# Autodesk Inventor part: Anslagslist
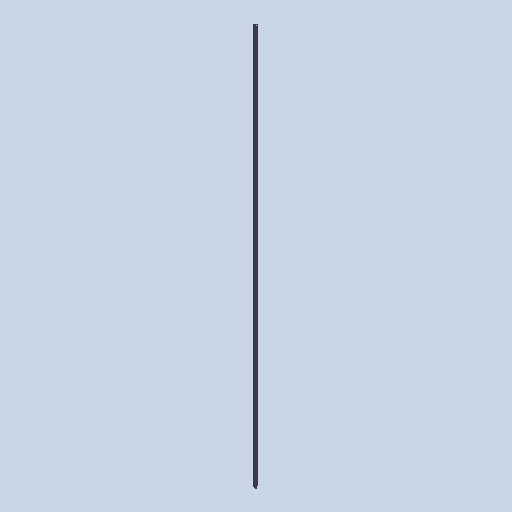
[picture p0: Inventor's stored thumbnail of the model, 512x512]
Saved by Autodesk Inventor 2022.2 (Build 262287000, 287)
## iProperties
Created: 2019-06
Part Number: Anslagslist
Material: Aluminum 6061, Welded
Document SubType Name: Modeling
Designer: cl
Density: 2.7 g/cm^3
Appearance: Weld - Aluminum
Author: cl
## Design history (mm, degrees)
sketch "Sketch1"
  geometry: L1 (0, 0)-(-19, 6.245); L2 (-19, 6.245)-(-29, 6.245); L3 (0, -3.158)-(-10, 0.129); L4 (0, 0)-(0, -3.158); L5 (-10, 0.129)-(-10, -14.871); L6 (-10, -14.871)-(-13, -14.871); L7 (-13, -14.871)-(-13, 1.115); L8 (-13, 1.115)-(-19.48, 3.245); L9 (-19.48, 3.245)-(-29, 3.245); L10 (-29, 3.245)-(-29, 6.245)
  constraints: 20 end point, 3 perpendicular, 2 horizontal, 2 parallel, 2 vertical, 1 collinear
  dimensions: "d0" = 3 distance between parallel lines of L3 L1; "d1" = 15 distance of L3.end L5.end; "d2" = 3 distance of L5.end L6.end; "d3" = 10 horizontal distance of L3.end L3.start; "d4" = 10 distance of L1.end L2.end; "d5" = 3 distance between parallel lines of L9 L2; "d6" = 20 distance of L1.start L1.end; "d8" = 29 distance between parallel lines of L10 L4
extrude "Extrusion1" new body sketch "Sketch1" distance "d11" = 2991 (computed from Daghöjd); taper "d12" = 0 deg
body "Solid1"
other parameters: "BladBredd" = 1338.66667, "Fönsterhöjd" = 862
